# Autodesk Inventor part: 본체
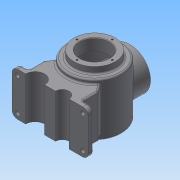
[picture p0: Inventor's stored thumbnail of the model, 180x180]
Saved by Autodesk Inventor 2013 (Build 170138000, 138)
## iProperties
Created: 2018-08
Part Number: 본체
Material: 일반
Document SubType Name: Modeling
Designer: Administrator
Density: 1 g/cm^3
Author: Administrator
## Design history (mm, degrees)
sketch "스케치1"
  geometry: L1 (0, 0)-(0, -108); L2 (0, 0)-(50, 0); L3 (50, 0)-(50, -96.671); L4 (50, -108)-(0, -108); L5 (50, -96.671)-(50, -108); A1 r 116 centre (0, 8) between (0, -108) and (50, -96.671)
  constraints: 10 end point, 4 perpendicular, 2 point on circle, 1 centre point, 1 tangent, 1 vertical
  dimensions: "d2" = 108 distance of L2.end L4.start; "d4" = 100 diameter of L3 L1; "d5" = 116 radius of A1
revolve "회전1" sketch "스케치1" stored, may be unused: angle "d6" = 90 deg
sketch "스케치2"
  geometry: C1 r 38 at (0, 0); 1 further point
  constraints: 1 centre point, 1 coincident
  dimensions: "d7" = 76 diameter of C1
extrude "돌출1" join sketch "스케치2" distance "d8" = 12; taper "d9" = 0 deg
sketch "스케치3"
  geometry: L1 (40, -90.163)-(40, -10); L2 (40, -10)-(0, -10); L3 (38, 12)-(-38, 12) reference; L4 (0, -10)-(0, -98); A1 r 116 centre (0, 8) between (-50, -96.671) and (50, -96.671) reference; A2 r 106 centre (0, 8) between (0, -98) and (40, -90.163); 2 further points
  constraints: 6 end point, 3 point on circle, 2 vertical alignment, 1 centre point, 1 vertical
  dimensions: "d10" = 10 radial gap between concentric circles of A1 A2; "d12" = 22 distance between parallel lines of L3 L2; "d13" = 80 diameter of L1 L4
revolve "회전2" sketch "스케치3" stored, may be unused: angle "d14" = 90 deg
hole "구멍1" diameter "d17" = 54; stored, may be unused: countersink angle "d21" = 90 deg, drill point angle "d23" = 0 deg; dims "d15" = 10, "d16" = 10, "d18" = 6, "d19" = 4, "d20" = 2, "d22" = 22
sketch "스케치4"
  geometry: 2 further points
  constraints: 1 vertical alignment
  dimensions: "d24" = 32.5 distance of point (0, 0) point (0, 32.5)
hole "구멍2" sketch "스케치4" at (0, 32.5) diameter "d25" = 3.242; stored, may be unused: countersink angle "d29" = 90 deg, drill point angle "d31" = 118 deg; dims "d26" = 8, "d27" = 4, "d28" = 2, "d30" = 10
node "작업 평면1"
sketch "스케치5"
  geometry: L1 (-50, -72)-(-70, -72); L2 (-70, -72)-(-70, -82); L3 (-70, -82)-(-45, -82); L4 (70, -82)-(70, -72); L5 (70, -72)-(50, -72); L6 (-10, -82)-(10, -82); L7 (35, -82)-(70, -82); L8 (-70, -72)-(-40.304, -29.59); L9 (70, -72)-(40.304, -29.59); L10 (-50, -72)-(-50, -43.437); L11 (50, -72)-(50, -43.437); L12 (-50, -43.437)-(-40.304, -29.59); L13 (50, -43.437)-(40.304, -29.59); A1 r 17.5 centre (-27.5, -82) between (-10, -82) and (-45, -82); A2 r 12.5 centre (22.5, -82) between (35, -82) and (10, -82); A3 r 50 centre (0, 0) between (-40.304, -29.59) and (40.304, -29.59); 3 further points
  constraints: 26 end point, 9 perpendicular, 6 point on circle, 5 point on line, 3 centre point, 2 collinear, 2 horizontal alignment, 1 coincident, 1 parallel, 3 other
  dimensions: "d41" = 17.5 radius of A1; "d42" = 12.5 radius of A2; "d43" = 27.5 horizontal distance of A1.centre point (0, 0); "d44" = 22.5 horizontal distance of A2.centre point (0, 0); "d45" = 10 distance of L1.end L2.end; "d46" = 140 distance of L2.end L4.start; "d47" = 70 distance from line of L4 point (0, 0); "d48" = 82 distance from line of L3 point (0, 0); "d55" = 20 distance of L4.end L5.end; "d114" = 35 deg angle of L8 L2; "d115" = 35 deg angle of L4 L9; "d116" = 20 distance of L1.start L1.end
extrude "돌출2" join sketch "스케치5" distance "d60" = 80; taper "d61" = 0 deg
fillet "모깎기1" dims "d62" = 10
sketch "스케치6"
  geometry: A1 r 10 centre (-10, 70) between (-10, 80) and (-20, 70) reference; A2 r 10 centre (-10, 10) between (-20, 10) and (-10, 0) reference; A3 r 10 centre (110, 10) between (110, 0) and (120, 10) reference; A4 r 10 centre (110, 70) between (120, 70) and (110, 80) reference; 5 further points
  constraints: 4 coincident
hole "구멍3" sketch "스케치6" at (-10, 70), (-10, 10), (110, 10), (110, 70) diameter "d63" = 8; stored, may be unused: countersink angle "d67" = 90 deg, drill point angle "d69" = 118 deg; dims "d64" = 8, "d65" = 4, "d66" = 2, "d68" = 10
node "작업 평면2"
sketch "스케치7"
  geometry: L1 (-15, 88)-(85, 88) reference; C1 r 38 at (35, 38); 1 further point
  constraints: 1 centre point, 1 vertical alignment
  dimensions: "d72" = 76 diameter of C1; "d74" = 50 distance from line of C1.centre L1
extrude "돌출3" join sketch "스케치7" stored distance "d75" = 80; taper "d76" = 0 deg
hole "구멍4" diameter "d79" = 54; stored, may be unused: countersink angle "d83" = 90 deg, drill point angle "d85" = 0 deg; dims "d80" = 8, "d81" = 4, "d82" = 2, "d84" = 10, "d86" = 10, "d87" = 10
sketch "스케치8"
  geometry: C1 r 27 at (0, 0) reference; 2 further points
  constraints: 1 vertical alignment
  dimensions: "d88" = 32.5 distance of C1.centre point (0, 32.5)
hole "구멍5" sketch "스케치8" at (0, 32.5) diameter "d89" = 3.242; stored, may be unused: countersink angle "d93" = 90 deg, drill point angle "d95" = 118 deg; dims "d90" = 8, "d91" = 4, "d92" = 2, "d94" = 10
node "작업 평면3"
sketch "스케치9"
  geometry: C1 r 32.5 at (0, 0); 1 further point
  constraints: 1 centre point, 1 coincident, 1 other
  dimensions: "d100" = 65 diameter of C1
feature "엠보싱1" sketch "스케치9" dims "d2" = 108, "d4" = 100, "d5" = 116, "d10" = 10, "d12" = 22, "d13" = 80, "d101" = 0.5, "d102" = 0
fillet "모깎기5" dims "d106" = 3
fillet "모깎기6" dims "d107" = 3
fillet "모깎기7" dims "d108" = 3
fillet "모깎기9" dims "d110" = 3
chamfer "모따기1" distance "d111" = 1; stored, may be unused: second distance "d112" = 2, angle "d113" = 45 deg
fillet "모깎기10" dims "d117" = 3
fillet "모깎기11" dims "d118" = 3
node "솔리드1"
pattern_circular "원형 패턴1" dims angle "d33" = 360 deg
pattern_circular "원형 패턴2" dims angle "d97" = 360 deg
other parameters: "d35" = -8, "d70" = -147, "d99" = -239
